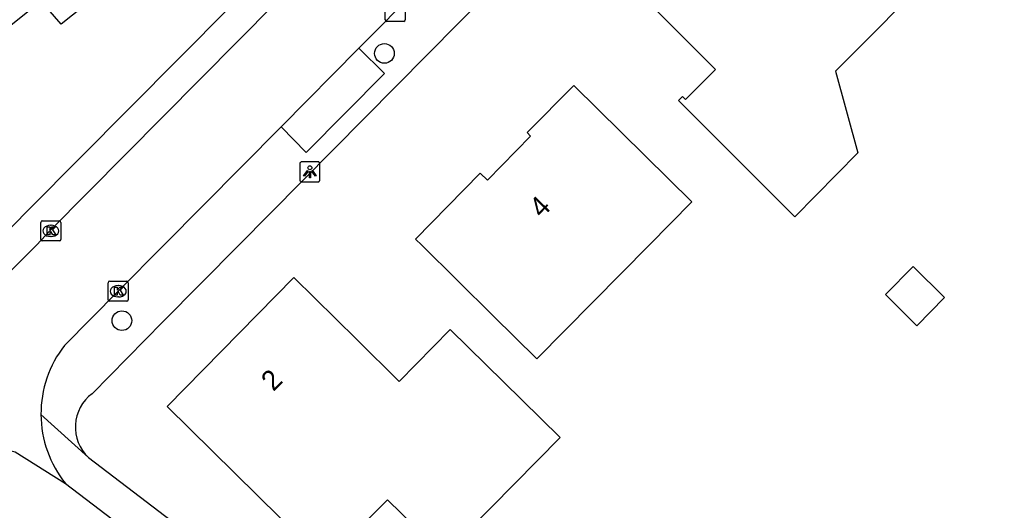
# Model space of a CAD drawing. Extents: x 159503 to 160347, y 382525 to 383272.
# Drawn here: x 159934.24 to 159983.69, y 382986.8 to 383011.22 of the extents above; entities that cross this region are included whole.
import ezdxf

# ---------------------------------------------------------------- set-up
doc = ezdxf.new("R2010")
doc.units = 0
for name, color, linetype in [('IMGEO_Boom', 7, 'Continuous'), ('IMGEO_Kolk', 7, 'Continuous'), ('IMGEO_Lichtpunt', 7, 'Continuous'), ('IMGEO_Pand', 7, 'Continuous'), ('IMGEO_Pand_nummerreeks', 7, 'Continuous'), ('IMGEO_Rijbaan_lokaal_open', 7, 'Continuous'), ('IMGEO_Voetpad_open', 7, 'Continuous')]:
    doc.layers.add(name, color=color, linetype=linetype)

msp = doc.modelspace()

# ---------------------------------------------------------------- linework, layer by layer
at = {"layer": 'IMGEO_Boom'}
for centre in [(159952.41, 383009.55), (159939.33, 382996.241)]:
    msp.add_circle(centre, 0.489, dxfattribs=at)
at = {"layer": 'IMGEO_Kolk'}
for p, q in [((159952.45, 383011.224), (159952.45, 383012.076)), ((159953.451, 383012.076), (159953.451, 383011.224)), ((159953.377, 383011.15), (159952.525, 383011.15)), ((159935.286, 383000.286), (159935.286, 383001.138)), ((159935.361, 383001.212), (159936.213, 383001.212)), ((159935.774, 383000.992), (159935.799, 383000.992)), ((159936.287, 383001.138), (159936.287, 383000.286)), ((159935.797, 383000.432), (159935.772, 383000.432)), ((159936.213, 383000.212), (159935.361, 383000.212)), ((159938.646, 382997.28), (159938.646, 382998.132)), ((159938.721, 382998.206), (159939.573, 382998.206)), ((159939.134, 382997.986), (159939.159, 382997.986)), ((159939.647, 382998.132), (159939.647, 382997.28)), ((159939.157, 382997.426), (159939.132, 382997.426)), ((159939.573, 382997.206), (159938.721, 382997.206))]:
    msp.add_line(p, q, dxfattribs=at)
for points in [[(159952.45, 383011.224), (159952.45, 383012.076)], [(159953.451, 383012.076), (159953.451, 383011.224)], [(159953.377, 383011.15), (159952.525, 383011.15)], [(159935.286, 383000.286), (159935.286, 383001.138)], [(159935.361, 383001.212), (159936.213, 383001.212)], [(159935.607, 383000.912), (159935.73, 383000.912), (159935.73, 383000.761), (159935.86, 383000.912), (159936.024, 383000.912), (159935.878, 383000.761), (159936.031, 383000.512), (159935.879, 383000.512), (159935.794, 383000.676), (159935.73, 383000.609), (159935.73, 383000.512), (159935.607, 383000.512), (159935.607, 383000.912)], [(159936.287, 383001.138), (159936.287, 383000.286)], [(159936.213, 383000.212), (159935.361, 383000.212)], [(159938.646, 382997.28), (159938.646, 382998.132)], [(159938.721, 382998.206), (159939.573, 382998.206)], [(159938.967, 382997.906), (159939.09, 382997.906), (159939.09, 382997.755), (159939.22, 382997.906), (159939.384, 382997.906), (159939.238, 382997.755), (159939.391, 382997.506), (159939.239, 382997.506), (159939.154, 382997.67), (159939.09, 382997.603), (159939.09, 382997.506), (159938.967, 382997.506), (159938.967, 382997.906)], [(159939.647, 382998.132), (159939.647, 382997.28)], [(159939.573, 382997.206), (159938.721, 382997.206)]]:
    msp.add_lwpolyline(points, dxfattribs=at)
for centre, start, end in [((159952.527, 383011.226), 181.552, 268.448), ((159952.527, 383011.226), 181.552, 268.448), ((159953.375, 383011.226), 271.552, 358.448), ((159953.375, 383011.226), 271.552, 358.448), ((159935.363, 383001.136), 91.552, 178.448), ((159935.363, 383001.136), 91.552, 178.448), ((159936.211, 383001.136), 1.552, 88.448), ((159936.211, 383001.136), 1.552, 88.448), ((159935.363, 383000.288), 181.552, 268.448), ((159935.363, 383000.288), 181.552, 268.448), ((159936.211, 383000.288), 271.552, 358.448), ((159936.211, 383000.288), 271.552, 358.448), ((159938.723, 382998.13), 91.552, 178.448), ((159938.723, 382998.13), 91.552, 178.448), ((159939.571, 382998.13), 1.552, 88.448), ((159939.571, 382998.13), 1.552, 88.448), ((159938.723, 382997.282), 181.552, 268.448), ((159938.723, 382997.282), 181.552, 268.448), ((159939.571, 382997.282), 271.552, 358.448), ((159939.571, 382997.282), 271.552, 358.448)]:
    msp.add_arc(centre, 0.0765, start, end, dxfattribs=at)
for centre, major_axis, ratio, start_param, end_param in [((159935.773, 383000.712), (-0.387, 0.002), 0.722429, 4.712389, 7.853982), ((159935.798, 383000.712), (-0.39, 0.002), 0.717154, 1.570796, 4.712389), ((159939.133, 382997.706), (-0.387, 0.002), 0.722429, 4.712389, 7.853982), ((159939.158, 382997.706), (-0.39, 0.002), 0.717154, 1.570796, 4.712389)]:
    msp.add_ellipse(centre, major_axis=major_axis, ratio=ratio, start_param=start_param, end_param=end_param, dxfattribs=at)
at = {"layer": 'IMGEO_Lichtpunt'}
for p, q in [((159948.196, 383004.057), (159948.196, 383003.25)), ((159948.196, 383004.057), (159948.196, 383003.25)), ((159949.098, 383004.152), (159948.29, 383004.152)), ((159949.098, 383004.152), (159948.29, 383004.152)), ((159949.192, 383003.25), (159949.192, 383004.057)), ((159949.192, 383003.25), (159949.192, 383004.057)), ((159948.29, 383003.156), (159949.098, 383003.156)), ((159948.29, 383003.156), (159949.098, 383003.156))]:
    msp.add_line(p, q, dxfattribs=at)
for points in [[(159948.57, 383003.721), (159948.609, 383003.693), (159948.421, 383003.431), (159948.383, 383003.458), (159948.57, 383003.721)], [(159948.672, 383003.673), (159948.719, 383003.673), (159948.719, 383003.351), (159948.672, 383003.351), (159948.672, 383003.673)], [(159948.782, 383003.693), (159948.82, 383003.72), (159949.007, 383003.458), (159948.968, 383003.43), (159948.782, 383003.693)]]:
    msp.add_lwpolyline(points, dxfattribs=at)
msp.add_circle((159948.695, 383003.855), 0.0994, dxfattribs=at)
for centre, start, end in [((159948.29, 383004.057), 90, 180), ((159948.29, 383004.057), 90, 180), ((159949.098, 383004.057), 0, 90), ((159949.098, 383004.057), 0, 90), ((159948.29, 383003.25), 180, 270), ((159948.29, 383003.25), 180, 270), ((159949.098, 383003.25), 270, 0), ((159949.098, 383003.25), 270, 360)]:
    msp.add_arc(centre, 0.0946, start, end, dxfattribs=at)
at = {"layer": 'IMGEO_Pand'}
for points in [[(159934.607, 383023.679), (159937.389, 383020.178), (159940.5, 383016.264), (159939.742, 383015.645), (159940.661, 383014.477), (159936.296, 383011.004), (159935.312, 383012.158), (159934.206, 383011.278), (159929.175, 383007.274), (159926.065, 383011.19), (159923.902, 383013.912), (159927.587, 383016.839), (159926.974, 383017.613), (159934.607, 383023.679)], [(159974.891, 383008.662), (159975.996, 383004.592), (159972.853, 383001.418), (159967.057, 383007.206), (159967.262, 383007.411), (159967.418, 383007.256), (159968.909, 383008.749), (159965.866, 383011.787), (159969.736, 383015.708), (159971.215, 383017.206), (159970.564, 383017.814), (159973.308, 383020.573), (159976.861, 383017.055), (159980.062, 383013.885), (159974.891, 383008.662)], [(159965.407, 383004.45), (159967.731, 383002.163), (159965.595, 383000), (159960.002, 382994.338), (159957.827, 382996.487), (159954.269, 383000), (159953.963, 383000.302), (159957.182, 383003.594), (159957.552, 383003.245), (159959.681, 383005.434), (159959.519, 383005.605), (159961.844, 383007.958), (159965.407, 383004.45)], [(159980.324, 382997.388), (159978.941, 382995.991), (159977.371, 382997.545), (159978.755, 382998.942), (159980.324, 382997.388)], [(159961.16, 382990.415), (159958.888, 382988.116), (159955.382, 382984.566), (159952.57, 382987.322), (159949.454, 382984.218), (159941.58, 382991.973), (159947.894, 382998.384), (159951.029, 382995.297), (159953.143, 382993.216), (159955.69, 382995.802), (159959.253, 382992.294), (159961.16, 382990.415)]]:
    msp.add_lwpolyline(points, dxfattribs=at)
at = {"layer": 'IMGEO_Rijbaan_lokaal_open'}
for points in [[(159923.721, 382990.801), (159932.922, 383000), (159934.742, 383001.82), (159994.392, 383061.861)], [(159995.495, 383061.001), (159935.774, 383000.752), (159935.074, 383000), (159925.512, 382990.469)], [(159951.133, 383009.814), (159969.218, 383028.009)], [(159947.26, 383005.903), (159951.133, 383009.814)], [(159936.469, 382995.009), (159939.149, 382997.71), (159941.416, 383000), (159947.26, 383005.903)], [(159921.709, 382987.969), (159927.002, 382989.777), (159931.031, 382990.397), (159934.007, 382989.715), (159936.514, 382988.127)], [(159936.514, 382988.127), (159946.588, 382980.466), (159971.819, 382961.325)]]:
    msp.add_lwpolyline(points, dxfattribs=at)
for centre, radius, start, end in [((159940.844, 382991.596), 5.549, 142.037, 180.3671), ((159940.85, 382991.6), 5.555, 180.4087, 218.6895)]:
    msp.add_arc(centre, radius, start, end, dxfattribs=at)
at = {"layer": 'IMGEO_Voetpad_open'}
for points in [[(160000.612, 383056.034), (160000, 383055.416), (159945.155, 383000), (159941.372, 382996.178), (159937.839, 382992.604)], [(159951.133, 383009.814), (159952.406, 383008.551), (159948.518, 383004.622), (159947.26, 383005.903)], [(159935.295, 382991.56), (159937.661, 382989.432)], [(159937.661, 382989.432), (159947.551, 382981.884), (159972.788, 382962.692), (159974.862, 382962.113), (159982.324, 382962.546)]]:
    msp.add_lwpolyline(points, dxfattribs=at)
msp.add_arc((159939.088, 382990.943), 2.078, 126.9416, 226.6347, dxfattribs=at)

# ---------------------------------------------------------------- texts
at = {"layer": 'IMGEO_Pand_nummerreeks'}
for s, rotation, p in [('4', 45.7961, (159960.247, 383001.311)), ('2', 45.4367, (159946.879, 382992.68))]:
    msp.add_text(s, height=1, rotation=rotation, dxfattribs=at).set_placement(p)

doc.saveas('drawing.dxf')
